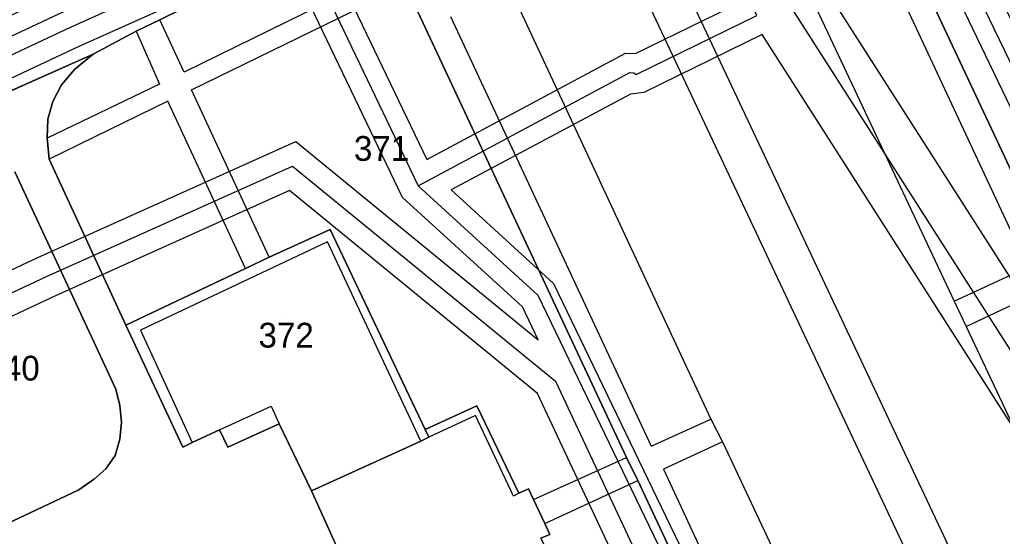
# Model space of a CAD drawing. Extents: x -264070 to -262271, y -1238894 to -1238141.
# Drawn here: x -263683.6 to -263604.2, y -1238650.1 to -1238608.4 of the extents above; entities that cross this region are included whole.
import ezdxf

# ---------------------------------------------------------------- set-up
doc = ezdxf.new("R2010")
doc.units = 0
for name, color, linetype in [('body_kn', 7, 'Continuous'), ('kladpar_druhypozemkov', 7, 'Continuous'), ('kladpar_hranice', 7, 'Continuous'), ('kladpar_parcelnecisla', 7, 'Continuous'), ('kladpar_plochy', 7, 'Continuous'), ('linie', 7, 'Continuous'), ('tarchy_linie', 7, 'Continuous'), ('zappar_hrandruhpozemk', 7, 'Continuous')]:
    doc.layers.add(name, color=color, linetype=linetype)

msp = doc.modelspace()

# ---------------------------------------------------------------- linework, layer by layer
at = {"layer": 'body_kn'}
for p, q in [((-263672.25, -1238608.4), (-263672.25, -1238608.4)), ((-263679.55, -1238609.04), (-263679.55, -1238609.04)), ((-263674.17, -1238609.32), (-263674.17, -1238609.32)), ((-263674.17, -1238609.32), (-263674.17, -1238609.32)), ((-263623.61, -1238609.58), (-263623.61, -1238609.58)), ((-263678.84, -1238610.58), (-263678.84, -1238610.58)), ((-263677.63, -1238611.17), (-263677.63, -1238611.17)), ((-263634.64, -1238611.1), (-263634.64, -1238611.1)), ((-263633.83, -1238611.12), (-263633.83, -1238611.12)), ((-263679.12, -1238612.38), (-263679.12, -1238612.38)), ((-263670.3, -1238612.63), (-263670.3, -1238612.63)), ((-263634.28, -1238612.66), (-263634.28, -1238612.66)), ((-263633.98, -1238612.67), (-263633.98, -1238612.67)), ((-263633.77, -1238612.82), (-263633.77, -1238612.82)), ((-263672.28, -1238613.58), (-263672.28, -1238613.58)), ((-263680.2, -1238613.65), (-263680.2, -1238613.65)), ((-263669.69, -1238614.04), (-263669.69, -1238614.04)), ((-263634.23, -1238614.39), (-263634.23, -1238614.39)), ((-263633.16, -1238614.25), (-263633.16, -1238614.25)), ((-263680.9, -1238614.98), (-263680.9, -1238614.98)), ((-263671.6, -1238614.95), (-263671.6, -1238614.95)), ((-263681.31, -1238616.42), (-263681.31, -1238616.42)), ((-263681.34, -1238617.94), (-263681.34, -1238617.94)), ((-263661.27, -1238618.22), (-263661.27, -1238618.22)), ((-263681.18, -1238619.65), (-263681.18, -1238619.65)), ((-263650.7, -1238619.66), (-263650.7, -1238619.66)), ((-263661.53, -1238620.2), (-263661.53, -1238620.2)), ((-263661.79, -1238622.18), (-263661.79, -1238622.18)), ((-263651.39, -1238621.79), (-263651.39, -1238621.79)), ((-263651.39, -1238621.79), (-263651.39, -1238621.79)), ((-263648.72, -1238622.12), (-263648.72, -1238622.12)), ((-263652.66, -1238622.73), (-263652.66, -1238622.73)), ((-263658.49, -1238625.31), (-263658.49, -1238625.31)), ((-263658.49, -1238625.31), (-263658.49, -1238625.31)), ((-263658.7, -1238626.31), (-263658.7, -1238626.31)), ((-263682.11, -1238627.57), (-263682.11, -1238627.57)), ((-263663.43, -1238627.56), (-263663.43, -1238627.56)), ((-263663.43, -1238627.56), (-263663.43, -1238627.56)), ((-263665.34, -1238628.48), (-263665.34, -1238628.48)), ((-263665.34, -1238628.48), (-263665.34, -1238628.48)), ((-263681.4, -1238629.12), (-263681.4, -1238629.12)), ((-263640.45, -1238629.67), (-263640.45, -1238629.67)), ((-263680.69, -1238630.67), (-263680.69, -1238630.67)), ((-263641.71, -1238630.62), (-263641.71, -1238630.62)), ((-263642.97, -1238631.57), (-263642.97, -1238631.57)), ((-263608.09, -1238631.11), (-263608.09, -1238631.11)), ((-263675, -1238633.03), (-263675, -1238633.03)), ((-263673.82, -1238633.45), (-263673.82, -1238633.45)), ((-263607.13, -1238633.16), (-263607.13, -1238633.16)), ((-263641.69, -1238634.22), (-263641.69, -1238634.22)), ((-263675.8, -1238638.2), (-263675.8, -1238638.2)), ((-263640.3, -1238637.56), (-263640.3, -1238637.56)), ((-263641.76, -1238638.57), (-263641.76, -1238638.57)), ((-263675.49, -1238639.52), (-263675.49, -1238639.52)), ((-263663.25, -1238639.57), (-263663.25, -1238639.57)), ((-263646.66, -1238639.54), (-263646.66, -1238639.54)), ((-263646.76, -1238640.33), (-263646.76, -1238640.33)), ((-263675.35, -1238640.88), (-263675.35, -1238640.88)), ((-263662.62, -1238641.01), (-263662.62, -1238641.01)), ((-263627.75, -1238640.63), (-263627.75, -1238640.63)), ((-263667.43, -1238641.48), (-263667.43, -1238641.48)), ((-263667.43, -1238641.48), (-263667.43, -1238641.48)), ((-263650.83, -1238641.47), (-263650.83, -1238641.47)), ((-263650.53, -1238642.07), (-263650.53, -1238642.07)), ((-263675.49, -1238642.25), (-263675.49, -1238642.25)), ((-263670.4, -1238642.88), (-263670.4, -1238642.88)), ((-263669.63, -1238642.51), (-263669.63, -1238642.51)), ((-263666.77, -1238642.89), (-263666.77, -1238642.89)), ((-263651.17, -1238642.4), (-263651.17, -1238642.4)), ((-263651.17, -1238642.4), (-263651.17, -1238642.4)), ((-263632.56, -1238642.81), (-263632.56, -1238642.81)), ((-263626.82, -1238642.47), (-263626.82, -1238642.47)), ((-263675.87, -1238643.57), (-263675.87, -1238643.57)), ((-263634.55, -1238643.73), (-263634.55, -1238643.73)), ((-263676.61, -1238644.63), (-263676.61, -1238644.63)), ((-263631.57, -1238644.66), (-263631.57, -1238644.66)), ((-263677.53, -1238645.44), (-263677.53, -1238645.44)), ((-263633.65, -1238645.59), (-263633.65, -1238645.59)), ((-263678.79, -1238646.32), (-263678.79, -1238646.32)), ((-263659.99, -1238646.42), (-263659.99, -1238646.42)), ((-263643.69, -1238646.84), (-263643.69, -1238646.84)), ((-263643.26, -1238646.6), (-263643.26, -1238646.6)), ((-263643.26, -1238646.6), (-263643.26, -1238646.6)), ((-263642.48, -1238646.25), (-263642.48, -1238646.25)), ((-263642.07, -1238647.11), (-263642.07, -1238647.11)), ((-263642.07, -1238647.11), (-263642.07, -1238647.11)), ((-263641.16, -1238649.06), (-263641.16, -1238649.06)), ((-263641.16, -1238649.06), (-263641.16, -1238649.06)), ((-263640.75, -1238649.95), (-263640.75, -1238649.95))]:
    msp.add_line(p, q, dxfattribs=at)
at = {"layer": 'kladpar_druhypozemkov'}
for p, q in [((-263654.42, -1238617.77), (-263654.42, -1238617.77)), ((-263661.99, -1238632.31), (-263661.99, -1238632.31))]:
    msp.add_line(p, q, dxfattribs=at)
at = {"layer": 'kladpar_hranice'}
for points in [[(-263686, -1238608.11), (-263668.83, -1238599.81), (-263667.32, -1238599.06), (-263658.25, -1238594.74), (-263656.28, -1238593.79), (-263653.2, -1238598.95), (-263655.1, -1238599.92), (-263672.25, -1238608.4), (-263674.17, -1238609.32), (-263677.63, -1238611.17), (-263692.98, -1238617.98)], [(-263641.47, -1238650.22), (-263640.75, -1238649.95), (-263641.16, -1238649.06), (-263642.07, -1238647.11), (-263642.48, -1238646.25), (-263643.26, -1238646.6), (-263646.66, -1238639.54), (-263650.83, -1238641.47), (-263658.49, -1238625.31), (-263663.43, -1238627.56), (-263665.34, -1238628.48), (-263675, -1238633.03), (-263681.18, -1238619.65), (-263681.34, -1238617.94), (-263681.31, -1238616.42), (-263680.9, -1238614.98), (-263680.2, -1238613.65), (-263679.12, -1238612.38), (-263677.63, -1238611.17), (-263674.17, -1238609.32), (-263672.25, -1238608.4), (-263655.1, -1238599.92)], [(-263580.6, -1238656.55), (-263577.28, -1238663.59), (-263576.42, -1238665.41), (-263571.45, -1238675.92), (-263571.12, -1238676.62), (-263567.73, -1238675.07), (-263565.87, -1238679.14), (-263565, -1238681.04), (-263561.19, -1238689.35), (-263557.8, -1238696.75), (-263556.88, -1238698.74), (-263565, -1238702.46), (-263565.87, -1238700.61), (-263573.22, -1238684.97), (-263574.13, -1238683.02), (-263581.37, -1238667.63), (-263582.21, -1238665.86), (-263590.39, -1238648.45), (-263591.3, -1238646.51), (-263599.33, -1238629.43), (-263600.25, -1238627.45), (-263612.87, -1238600.61)], [(-263612.87, -1238600.61), (-263600.25, -1238627.45), (-263599.33, -1238629.43), (-263591.3, -1238646.51), (-263590.39, -1238648.45), (-263582.21, -1238665.86), (-263581.37, -1238667.63), (-263574.13, -1238683.02)], [(-263652.42, -1238605.6), (-263634.55, -1238643.73), (-263633.65, -1238645.59), (-263625.62, -1238662.7)], [(-263614.05, -1238720.29), (-263623.38, -1238700.66), (-263619.42, -1238698.77), (-263618.9, -1238698.51), (-263612.56, -1238694.84), (-263612.27, -1238693.43), (-263612.25, -1238692.1), (-263612.45, -1238690.67), (-263615.57, -1238684.02), (-263616.51, -1238682.09), (-263624.69, -1238664.66), (-263625.62, -1238662.7), (-263633.65, -1238645.59), (-263634.55, -1238643.73), (-263652.42, -1238605.6)], [(-263692.98, -1238617.98), (-263677.63, -1238611.17), (-263679.12, -1238612.38), (-263680.2, -1238613.65), (-263680.9, -1238614.98), (-263681.31, -1238616.42), (-263681.34, -1238617.94), (-263681.18, -1238619.65), (-263675, -1238633.03), (-263670.4, -1238642.88), (-263669.63, -1238642.51), (-263667.43, -1238641.48), (-263666.77, -1238642.89), (-263662.62, -1238641.01), (-263659.99, -1238646.42), (-263657.46, -1238652.01)], [(-263683.95, -1238620.66), (-263675.8, -1238638.2), (-263675.49, -1238639.52), (-263675.35, -1238640.88), (-263675.49, -1238642.25), (-263675.87, -1238643.57), (-263676.61, -1238644.63), (-263677.53, -1238645.44), (-263678.79, -1238646.32), (-263688, -1238650.67)], [(-263688, -1238650.67), (-263678.79, -1238646.32), (-263677.53, -1238645.44), (-263676.61, -1238644.63), (-263675.87, -1238643.57), (-263675.49, -1238642.25), (-263675.35, -1238640.88), (-263675.49, -1238639.52), (-263675.8, -1238638.2), (-263683.95, -1238620.66)], [(-263658.49, -1238625.31), (-263650.83, -1238641.47), (-263650.53, -1238642.07), (-263651.17, -1238642.4), (-263659.99, -1238646.42), (-263662.62, -1238641.01), (-263666.77, -1238642.89), (-263667.43, -1238641.48), (-263669.63, -1238642.51), (-263670.4, -1238642.88), (-263675, -1238633.03), (-263665.34, -1238628.48), (-263663.43, -1238627.56), (-263658.49, -1238625.31)], [(-263651.17, -1238642.4), (-263650.53, -1238642.07), (-263650.83, -1238641.47), (-263646.66, -1238639.54), (-263643.26, -1238646.6), (-263642.48, -1238646.25), (-263642.07, -1238647.11), (-263641.16, -1238649.06), (-263640.75, -1238649.95), (-263641.47, -1238650.22), (-263637.64, -1238658.42), (-263638.11, -1238658.63), (-263651.44, -1238664.69), (-263655.98, -1238655.11), (-263658.83, -1238656.42), (-263659.13, -1238655.68), (-263659.99, -1238653.81), (-263660.23, -1238653.3), (-263657.46, -1238652.01), (-263659.99, -1238646.42), (-263651.17, -1238642.4)]]:
    msp.add_lwpolyline(points, dxfattribs=at)
at = {"layer": 'kladpar_plochy'}
for p, q in [((-263692.98, -1238617.98), (-263677.63, -1238611.17)), ((-263677.63, -1238611.17), (-263679.12, -1238612.38)), ((-263679.12, -1238612.38), (-263680.2, -1238613.65)), ((-263680.2, -1238613.65), (-263680.9, -1238614.98)), ((-263680.9, -1238614.98), (-263681.31, -1238616.42)), ((-263681.31, -1238616.42), (-263681.34, -1238617.94)), ((-263681.34, -1238617.94), (-263681.18, -1238619.65)), ((-263681.18, -1238619.65), (-263675, -1238633.03)), ((-263675.8, -1238638.2), (-263683.95, -1238620.66)), ((-263675, -1238633.03), (-263670.4, -1238642.88)), ((-263675.49, -1238639.52), (-263675.8, -1238638.2)), ((-263675.35, -1238640.88), (-263675.49, -1238639.52)), ((-263675.49, -1238642.25), (-263675.35, -1238640.88)), ((-263666.77, -1238642.89), (-263662.62, -1238641.01)), ((-263662.62, -1238641.01), (-263659.99, -1238646.42)), ((-263669.63, -1238642.51), (-263667.43, -1238641.48)), ((-263667.43, -1238641.48), (-263666.77, -1238642.89)), ((-263675.87, -1238643.57), (-263675.49, -1238642.25)), ((-263670.4, -1238642.88), (-263669.63, -1238642.51)), ((-263676.61, -1238644.63), (-263675.87, -1238643.57)), ((-263677.53, -1238645.44), (-263676.61, -1238644.63)), ((-263678.79, -1238646.32), (-263677.53, -1238645.44)), ((-263688, -1238650.67), (-263678.79, -1238646.32)), ((-263659.99, -1238646.42), (-263657.46, -1238652.01))]:
    msp.add_line(p, q, dxfattribs=at)
for points in [[(-263687.42, -1238608.78), (-263686, -1238608.11), (-263668.83, -1238599.81), (-263667.32, -1238599.06), (-263658.25, -1238594.74), (-263656.28, -1238593.79), (-263653.2, -1238598.95), (-263655.1, -1238599.92), (-263672.25, -1238608.4), (-263674.17, -1238609.32), (-263677.63, -1238611.17), (-263692.98, -1238617.98), (-263715.64, -1238628.72), (-263727.01, -1238634.34), (-263731.32, -1238636.34), (-263733.14, -1238637.18), (-263746.1, -1238643.1), (-263749.05, -1238638.31), (-263740.04, -1238634.05), (-263738.66, -1238633.4), (-263723.45, -1238626.11), (-263721.85, -1238625.34), (-263705.34, -1238617.4), (-263703.93, -1238616.68)], [(-263658.49, -1238625.31), (-263650.83, -1238641.47), (-263650.53, -1238642.07), (-263651.17, -1238642.4), (-263659.99, -1238646.42), (-263662.62, -1238641.01), (-263666.77, -1238642.89), (-263667.43, -1238641.48), (-263669.63, -1238642.51), (-263670.4, -1238642.88), (-263675, -1238633.03), (-263665.34, -1238628.48), (-263663.43, -1238627.56)], [(-263651.17, -1238642.4), (-263650.53, -1238642.07), (-263650.83, -1238641.47), (-263646.66, -1238639.54), (-263643.26, -1238646.6), (-263642.48, -1238646.25), (-263642.07, -1238647.11), (-263641.16, -1238649.06), (-263640.75, -1238649.95), (-263641.47, -1238650.22), (-263637.64, -1238658.42), (-263638.11, -1238658.63), (-263651.44, -1238664.69), (-263655.98, -1238655.11), (-263658.83, -1238656.42), (-263659.13, -1238655.68), (-263659.99, -1238653.81), (-263660.23, -1238653.3), (-263657.46, -1238652.01), (-263659.99, -1238646.42)]]:
    msp.add_lwpolyline(points, close=True, dxfattribs=at)
for points in [[(-263641.47, -1238650.22), (-263640.75, -1238649.95), (-263641.16, -1238649.06), (-263642.07, -1238647.11), (-263642.48, -1238646.25), (-263643.26, -1238646.6), (-263646.66, -1238639.54), (-263650.83, -1238641.47), (-263658.49, -1238625.31), (-263663.43, -1238627.56), (-263665.34, -1238628.48), (-263675, -1238633.03), (-263681.18, -1238619.65), (-263681.34, -1238617.94), (-263681.31, -1238616.42), (-263680.9, -1238614.98), (-263680.2, -1238613.65), (-263679.12, -1238612.38), (-263677.63, -1238611.17), (-263674.17, -1238609.32), (-263672.25, -1238608.4), (-263655.1, -1238599.92)], [(-263600.25, -1238627.45), (-263612.87, -1238600.61)], [(-263612.87, -1238600.61), (-263600.25, -1238627.45), (-263599.33, -1238629.43), (-263591.3, -1238646.51), (-263590.39, -1238648.45), (-263582.21, -1238665.86), (-263581.37, -1238667.63), (-263574.13, -1238683.02), (-263573.22, -1238684.97), (-263565.87, -1238700.61), (-263565, -1238702.46), (-263558.88, -1238715.6), (-263561.04, -1238716.56)], [(-263652.42, -1238605.6), (-263634.55, -1238643.73), (-263633.65, -1238645.59), (-263625.62, -1238662.7)], [(-263614.05, -1238720.29), (-263623.38, -1238700.66), (-263619.42, -1238698.77), (-263618.9, -1238698.51), (-263612.56, -1238694.84), (-263612.27, -1238693.43), (-263612.25, -1238692.1), (-263612.45, -1238690.67), (-263615.57, -1238684.02), (-263616.51, -1238682.09), (-263624.69, -1238664.66), (-263625.62, -1238662.7), (-263633.65, -1238645.59), (-263634.55, -1238643.73), (-263652.42, -1238605.6)], [(-263683.95, -1238620.66), (-263675.8, -1238638.2), (-263675.49, -1238639.52), (-263675.35, -1238640.88), (-263675.49, -1238642.25), (-263675.87, -1238643.57), (-263676.61, -1238644.63), (-263677.53, -1238645.44), (-263678.79, -1238646.32), (-263688, -1238650.67)]]:
    msp.add_lwpolyline(points, dxfattribs=at)
at = {"layer": 'linie'}
for p, q in [((-263689.35, -1238479.53), (-263551.75, -1238771.36)), ((-263554.69, -1238772.72), (-263692.34, -1238480.82))]:
    msp.add_line(p, q, dxfattribs=at)
at = {"layer": 'tarchy_linie'}
msp.add_line((-263609.63, -1238599.24), (-263560.86, -1238700.56), dxfattribs=at)
for points in [[(-263651.39, -1238621.79), (-263634.28, -1238612.66), (-263633.98, -1238612.67), (-263633.77, -1238612.82), (-263624.03, -1238608.06), (-263624.37, -1238607.36), (-263623.97, -1238607.16), (-263609.63, -1238599.24), (-263559.99, -1238575.98), (-263511.52, -1238553.93), (-263501.34, -1238575.51)], [(-263709.16, -1238640.24), (-263682.11, -1238627.57), (-263661.27, -1238618.22), (-263641.69, -1238634.22), (-263642.97, -1238631.57), (-263652.66, -1238622.73), (-263661.97, -1238603.32), (-263660.58, -1238602.63), (-263659.19, -1238601.94), (-263650.7, -1238619.66), (-263634.64, -1238611.1), (-263633.83, -1238611.12), (-263626.1, -1238607.35), (-263626.43, -1238606.66), (-263625.71, -1238606.3), (-263635.59, -1238590.85), (-263632.71, -1238589.52), (-263629.82, -1238588.19)], [(-263632.71, -1238589.52), (-263594.36, -1238649.43), (-263568, -1238705.98), (-263563.18, -1238706.37)], [(-263749.03, -1238638.34), (-263662.87, -1238597.99), (-263655.9, -1238594.42), (-263655.11, -1238595.75), (-263654.03, -1238597.57), (-263653.2, -1238598.95), (-263655.02, -1238599.88), (-263659.27, -1238601.79), (-263659.19, -1238601.94), (-263660.58, -1238602.63), (-263661.97, -1238603.32), (-263662.1, -1238603.06), (-263678.84, -1238610.58), (-263714.33, -1238627.24), (-263744.27, -1238641.77), (-263746.39, -1238642.63), (-263747.29, -1238641.16), (-263748.22, -1238639.66), (-263749.03, -1238638.34)], [(-263655.11, -1238595.75), (-263662.22, -1238599.38), (-263748.22, -1238639.66)], [(-263654.03, -1238597.57), (-263679.55, -1238609.04), (-263715.06, -1238625.71), (-263744.96, -1238640.22), (-263747.29, -1238641.16)], [(-263607.56, -1238599.98), (-263594.13, -1238627.86), (-263589.6, -1238637.45), (-263586.41, -1238644.22), (-263585.49, -1238646.18), (-263580.6, -1238656.55), (-263577.28, -1238663.59), (-263576.42, -1238665.41), (-263571.45, -1238675.92), (-263571.12, -1238676.62), (-263570.75, -1238676.45), (-263559.45, -1238699.92), (-263560.86, -1238700.56), (-263562.27, -1238701.21), (-263610.31, -1238601.39)], [(-263660.58, -1238602.63), (-263651.39, -1238621.79), (-263641.71, -1238630.62), (-263588.89, -1238740.14), (-263579.02, -1238737.95), (-263577.41, -1238737.07), (-263576.98, -1238736.9), (-263576.61, -1238737.68), (-263575.52, -1238737.16), (-263566.31, -1238732.75), (-263566.78, -1238731.77), (-263566.23, -1238731.51), (-263558.58, -1238727.98)], [(-263618.48, -1238605.9), (-263591.59, -1238647.91), (-263565.94, -1238702.94), (-263564.73, -1238703.03), (-263563.18, -1238706.37), (-263561.63, -1238709.71), (-263570.06, -1238709.02), (-263597.13, -1238650.95), (-263623.61, -1238609.58), (-263633.16, -1238614.25), (-263634.23, -1238614.39), (-263648.72, -1238622.12), (-263640.45, -1238629.67), (-263590.39, -1238733.46)], [(-263709.12, -1238667.95), (-263707.52, -1238641.35), (-263681.4, -1238629.12), (-263661.53, -1238620.2), (-263640.3, -1238637.56), (-263618.59, -1238683.83), (-263593.48, -1238736.77), (-263576.63, -1238729.18), (-263561.94, -1238722.36)], [(-263594.32, -1238739.07), (-263620.17, -1238684.58), (-263641.76, -1238638.57), (-263661.79, -1238622.18), (-263680.69, -1238630.67), (-263705.88, -1238642.46)]]:
    msp.add_lwpolyline(points, dxfattribs=at)
at = {"layer": 'zappar_hrandruhpozemk'}
for p, q in [((-263614.71, -1238601.49), (-263602.17, -1238628.35)), ((-263653.1, -1238604.18), (-263670.3, -1238612.63)), ((-263620.74, -1238604.27), (-263608.09, -1238631.11)), ((-263670.3, -1238612.63), (-263672.25, -1238608.4)), ((-263648.78, -1238608.12), (-263632.56, -1238642.81)), ((-263674.17, -1238609.32), (-263672.28, -1238613.58)), ((-263672.28, -1238613.58), (-263681.34, -1238617.94)), ((-263608.09, -1238631.11), (-263602.17, -1238628.35)), ((-263607.13, -1238633.16), (-263601.24, -1238630.35)), ((-263608.09, -1238631.11), (-263607.13, -1238633.16)), ((-263673.82, -1238633.45), (-263669.63, -1238642.51)), ((-263667.43, -1238641.48), (-263663.25, -1238639.57)), ((-263663.25, -1238639.57), (-263662.62, -1238641.01)), ((-263646.76, -1238640.33), (-263650.53, -1238642.07)), ((-263643.69, -1238646.84), (-263646.76, -1238640.33)), ((-263632.56, -1238642.81), (-263627.75, -1238640.63)), ((-263626.82, -1238642.47), (-263631.57, -1238644.66)), ((-263626.82, -1238642.47), (-263618.77, -1238659.5)), ((-263642.07, -1238647.11), (-263634.55, -1238643.73)), ((-263631.57, -1238644.66), (-263623.63, -1238661.76)), ((-263641.16, -1238649.06), (-263633.65, -1238645.59)), ((-263643.26, -1238646.6), (-263643.69, -1238646.84))]:
    msp.add_line(p, q, dxfattribs=at)
for points in [[(-263653.2, -1238598.95), (-263653.03, -1238598.91), (-263652.07, -1238598.66), (-263650.95, -1238598.52), (-263650.15, -1238598.66), (-263649.65, -1238598.75), (-263648.58, -1238599.26), (-263647.56, -1238599.9), (-263646.47, -1238600.91), (-263645.63, -1238602.31), (-263627.75, -1238640.63), (-263626.82, -1238642.47)], [(-263663.43, -1238627.56), (-263669.69, -1238614.04), (-263652.42, -1238605.6)], [(-263665.34, -1238628.48), (-263671.6, -1238614.95), (-263681.18, -1238619.65)], [(-263651.17, -1238642.4), (-263658.7, -1238626.31), (-263673.82, -1238633.45)], [(-263607.13, -1238633.16), (-263599.11, -1238650.15), (-263598.2, -1238652.09)]]:
    msp.add_lwpolyline(points, dxfattribs=at)

# ---------------------------------------------------------------- texts
at = {"layer": 'kladpar_parcelnecisla'}
for s, p in [('371', (-263656.575, -1238619.78)), ('372', (-263664.281, -1238634.85)), ('340', (-263686.413, -1238637.51))]:
    msp.add_text(s, height=2, dxfattribs=at).set_placement(p)

doc.saveas('drawing.dxf')
